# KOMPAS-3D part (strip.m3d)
File: created 18.09.2016 11:49:25, last saved 18.09.2016 11:56:26.
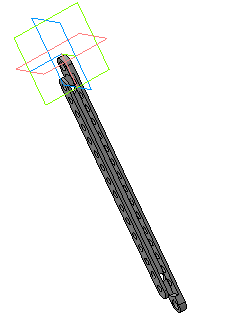
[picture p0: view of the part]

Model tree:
1. Эскиз:1
2. Операция выдавливания:1
     Расстояние 1 = 5
3. Эскиз:2
4. Операция выдавливания:2
     Расстояние 1 = 5
5. Эскиз:3
6. Вырезать элемент выдавливания:1
     Расстояние 2 = 9; Расстояние 1 = 9
7. Эскиз:4
8. Вырезать элемент выдавливания:2
     Расстояние 2 = 9; Расстояние 1 = 9
9. Эскиз:5
10. Вырезать элемент выдавливания:3
     Расстояние 2 = 9; Расстояние 1 = 19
